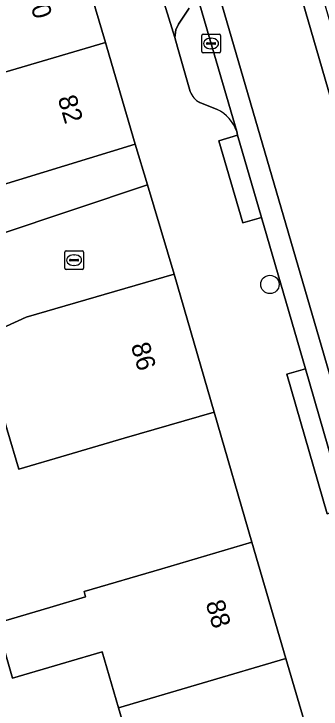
# Model space of a CAD drawing. Extents: x 159262 to 160143, y 383399 to 384319.
# Drawn here: x 159610.56 to 159626.93, y 383964.76 to 384001.77 of the extents above; entities that cross this region are included whole.
import ezdxf

# ---------------------------------------------------------------- set-up
doc = ezdxf.new("R2010")
doc.units = 0
for name, color, linetype in [('IMGEO_Boom', 7, 'Continuous'), ('IMGEO_Erf', 7, 'Continuous'), ('IMGEO_Kolk', 7, 'Continuous'), ('IMGEO_Pand', 7, 'Continuous'), ('IMGEO_Pand_nummerreeks', 7, 'Continuous'), ('IMGEO_Parkeervlak_open', 7, 'Continuous'), ('IMGEO_Rijbaan_lokaal_gesloten', 7, 'Continuous'), ('IMGEO_Verkeerseiland_open', 7, 'Continuous'), ('IMGEO_Voetpad_open', 7, 'Continuous')]:
    doc.layers.add(name, color=color, linetype=linetype)

msp = doc.modelspace()

# ---------------------------------------------------------------- linework, layer by layer
at = {"layer": 'IMGEO_Boom'}
msp.add_circle((159624.2, 383987.368), 0.489, dxfattribs=at)
at = {"layer": 'IMGEO_Erf'}
msp.add_lwpolyline([(159609.702, 383990.016), (159617.673, 383992.679), (159617.029, 383994.834), (159603.519, 383990.7), (159602.655, 383993.46), (159600.265, 383992.746), (159598.549, 383992.233), (159597.74, 383995.059), (159588.938, 383992.59), (159592.618, 383983.277), (159598.01, 383985.458), (159607.28, 383989.207)], close=True, dxfattribs=at)
msp.add_lwpolyline([(159617.064, 383961.667), (159616.136, 383964.825), (159615.258, 383967.811), (159613.337, 383967.246), (159610.494, 383966.411), (159609.635, 383969.336), (159612.478, 383970.171), (159614.385, 383970.731), (159614.301, 383971.02), (159618.438, 383972.236), (159623.235, 383973.646), (159621.234, 383980.578), (159616.434, 383979.18), (159613.365, 383978.285), (159610.819, 383977.543), (159610.212, 383979.628), (159609.303, 383982.748), (159603.513, 383980.094), (159607.678, 383971.028), (159584.038, 383960.27)], dxfattribs=at)
at = {"layer": 'IMGEO_Kolk'}
for p, q in [((159620.567, 383999.769), (159620.567, 384000.621)), ((159620.642, 384000.695), (159621.494, 384000.695)), ((159621.055, 384000.475), (159621.08, 384000.475)), ((159621.568, 384000.621), (159621.568, 383999.769)), ((159620.826, 384000.189), (159620.826, 384000.201)), ((159621.264, 384000.152), (159620.866, 384000.152)), ((159620.869, 384000.238), (159621.267, 384000.238)), ((159621.31, 384000.201), (159621.31, 384000.189)), ((159621.494, 383999.695), (159620.642, 383999.695)), ((159621.078, 383999.915), (159621.053, 383999.915)), ((159613.271, 383988.236), (159613.271, 383989.088)), ((159613.346, 383989.162), (159614.198, 383989.162)), ((159613.759, 383988.942), (159613.784, 383988.942)), ((159614.272, 383989.088), (159614.272, 383988.236)), ((159613.53, 383988.656), (159613.53, 383988.668)), ((159613.968, 383988.619), (159613.57, 383988.619)), ((159613.573, 383988.705), (159613.971, 383988.705)), ((159614.014, 383988.668), (159614.014, 383988.656)), ((159614.198, 383988.162), (159613.346, 383988.162)), ((159613.782, 383988.382), (159613.757, 383988.382))]:
    msp.add_line(p, q, dxfattribs=at)
for points in [[(159620.567, 383999.769), (159620.567, 384000.621)], [(159620.642, 384000.695), (159621.494, 384000.695)], [(159621.568, 384000.621), (159621.568, 383999.769)], [(159621.494, 383999.695), (159620.642, 383999.695)], [(159613.271, 383988.236), (159613.271, 383989.088)], [(159613.346, 383989.162), (159614.198, 383989.162)], [(159614.272, 383989.088), (159614.272, 383988.236)], [(159614.198, 383988.162), (159613.346, 383988.162)]]:
    msp.add_lwpolyline(points, dxfattribs=at)
for centre, radius, start, end in [((159620.644, 384000.619), 0.0765, 91.552, 178.448), ((159620.644, 384000.619), 0.0765, 91.552, 178.448), ((159621.492, 384000.619), 0.0765, 1.552, 88.448), ((159621.492, 384000.619), 0.0765, 1.552, 88.448), ((159620.866, 384000.198), 0.0403, 85.8775, 175.7526), ((159620.863, 384000.188), 0.0366, 178.938, 274.7102), ((159621.267, 384000.195), 0.043, 264.8664, 352.4533), ((159621.271, 384000.2), 0.0386, 1.7309, 96.639), ((159620.644, 383999.771), 0.0765, 181.552, 268.448), ((159620.644, 383999.771), 0.0765, 181.552, 268.448), ((159621.492, 383999.771), 0.0765, 271.552, 358.448), ((159621.492, 383999.771), 0.0765, 271.552, 358.448), ((159613.348, 383989.086), 0.0765, 91.552, 178.448), ((159613.348, 383989.086), 0.0765, 91.552, 178.448), ((159614.196, 383989.086), 0.0765, 1.552, 88.448), ((159614.196, 383989.086), 0.0765, 1.552, 88.448), ((159613.57, 383988.665), 0.0403, 85.8775, 175.7526), ((159613.567, 383988.655), 0.0366, 178.938, 274.7102), ((159613.971, 383988.662), 0.043, 264.8664, 352.4533), ((159613.975, 383988.667), 0.0386, 1.7309, 96.639), ((159613.348, 383988.238), 0.0765, 181.552, 268.448), ((159613.348, 383988.238), 0.0765, 181.552, 268.448), ((159614.196, 383988.238), 0.0765, 271.552, 358.448), ((159614.196, 383988.238), 0.0765, 271.552, 358.448)]:
    msp.add_arc(centre, radius, start, end, dxfattribs=at)
for centre, major_axis, ratio, start_param, end_param in [((159621.054, 384000.195), (-0.387, 0.002), 0.722429, 4.712389, 7.853982), ((159621.079, 384000.195), (-0.39, 0.002), 0.717154, 1.570796, 4.712389), ((159613.758, 383988.662), (-0.387, 0.002), 0.722429, 4.712389, 7.853982), ((159613.783, 383988.662), (-0.39, 0.002), 0.717154, 1.570796, 4.712389)]:
    msp.add_ellipse(centre, major_axis=major_axis, ratio=ratio, start_param=start_param, end_param=end_param, dxfattribs=at)
at = {"layer": 'IMGEO_Pand'}
for points in [[(159599.464, 383995.543), (159615.437, 384000.245), (159613.85, 384005.639), (159605.787, 384003.266), (159605.254, 384003.112), (159602.301, 384002.244), (159603.093, 383999.552), (159593.12, 383996.624), (159592.544, 383998.43), (159580.759, 383994.973), (159582.644, 383990.822), (159588.938, 383992.59), (159597.74, 383995.059)], [(159615.509, 384000), (159615.437, 384000.245), (159599.464, 383995.543), (159597.74, 383995.059), (159598.549, 383992.233), (159600.265, 383992.746), (159602.655, 383993.46), (159603.519, 383990.7), (159617.029, 383994.834)], [(159623.235, 383973.646), (159618.438, 383972.236), (159614.301, 383971.02), (159614.385, 383970.731), (159612.478, 383970.171), (159609.635, 383969.336), (159610.494, 383966.411), (159613.337, 383967.246), (159615.258, 383967.811), (159616.136, 383964.825), (159625.057, 383967.448)], [(159616.136, 383964.825), (159617.064, 383961.667), (159615.141, 383961.102), (159610.851, 383959.841), (159611.745, 383956.801), (159616.035, 383958.062), (159617.938, 383958.622), (159622.082, 383959.84), (159626.879, 383961.25), (159625.057, 383967.448)]]:
    msp.add_lwpolyline(points, close=True, dxfattribs=at)
msp.add_lwpolyline([(159568.187, 383962.73), (159569.09, 383963.023), (159569.26, 383962.497), (159581.93, 383966.6), (159584.038, 383960.27), (159607.678, 383971.028), (159603.513, 383980.094), (159609.303, 383982.748), (159610.212, 383979.628), (159610.819, 383977.543), (159613.365, 383978.285), (159616.434, 383979.18), (159621.234, 383980.578), (159619.095, 383987.923), (159611.223, 383985.63), (159600.104, 383980.555), (159580.294, 383971.513), (159581.043, 383969.342), (159567.313, 383964.895)], dxfattribs=at)
at = {"layer": 'IMGEO_Parkeervlak_open'}
for points in [[(159622.431, 383995.515), (159621.125, 384000), (159620.146, 384003.366)], [(159619.907, 384002.084), (159619.329, 384001.234), (159619.194, 384000.921), (159619.129, 384000.507), (159619.276, 384000), (159619.955, 383997.649)], [(159620.465, 383997.061), (159621.395, 383996.679)]]:
    msp.add_lwpolyline(points, dxfattribs=at)
for centre, radius, start, end in [((159620.908, 383997.96), 1.002, 198.0885, 243.7847), ((159620.576, 383994.907), 1.953, 18.1521, 65.1882)]:
    msp.add_arc(centre, radius, start, end, dxfattribs=at)
at = {"layer": 'IMGEO_Rijbaan_lokaal_gesloten'}
for points in [[(159613.293, 384030.894), (159638.993, 383942.811), (159642.94, 383943.962), (159619.532, 384024.506), (159617.87, 384030.824), (159617.785, 384031.248)], [(159618.934, 384031.339), (159617.785, 384031.248), (159617.87, 384030.824), (159619.532, 384024.506), (159642.94, 383943.962), (159644.044, 383944.284), (159627.798, 384000), (159621.981, 384019.881), (159619.292, 384029.772), (159618.998, 384031.049), (159618.966, 384031.194)], [(159638.993, 383942.811), (159613.293, 384030.894), (159612.139, 384030.718), (159616.014, 384017.294), (159618.072, 384010.257), (159620.044, 384003.715), (159620.146, 384003.366), (159621.125, 384000), (159622.431, 383995.515), (159622.476, 383995.308), (159623.756, 383990.941), (159626.097, 383982.875), (159628.25, 383975.445), (159628.423, 383974.819), (159628.483, 383974.613), (159631.364, 383964.812), (159631.817, 383963.34), (159632.881, 383959.719), (159634.562, 383953.952), (159635.597, 383950.281), (159635.943, 383949.139), (159637.889, 383942.489)]]:
    msp.add_lwpolyline(points, close=True, dxfattribs=at)
at = {"layer": 'IMGEO_Verkeerseiland_open'}
msp.add_lwpolyline([(159619.003, 384004.734), (159618.145, 384005.202), (159617.796, 384005.432), (159617.537, 384005.679), (159619.129, 384000.507), (159619.194, 384000.921), (159619.329, 384001.234), (159619.907, 384002.084)], dxfattribs=at)
at = {"layer": 'IMGEO_Voetpad_open'}
for points in [[(159619.955, 383997.649), (159619.276, 384000), (159619.129, 384000.507), (159617.537, 384005.679), (159616.373, 384009.758), (159611.186, 384027.442)], [(159613.85, 384005.639), (159615.437, 384000.245), (159615.509, 384000), (159617.029, 383994.834), (159617.673, 383992.679), (159619.095, 383987.923), (159621.234, 383980.578), (159623.235, 383973.646), (159625.057, 383967.448), (159626.879, 383961.25), (159627.564, 383958.843), (159629.447, 383952.41), (159629.277, 383952.36), (159630.084, 383949.406), (159630.309, 383949.472), (159631.947, 383943.875), (159634.034, 383936.746), (159635.482, 383931.797), (159637.133, 383926.157), (159638.703, 383920.791), (159638.888, 383920.16), (159633.406, 383906.478)], [(159621.395, 383996.679), (159620.465, 383997.061)], [(159625.098, 383982.586), (159626.097, 383982.875), (159623.756, 383990.941), (159622.758, 383990.648), (159621.478, 383995.015), (159622.476, 383995.308), (159622.431, 383995.515)], [(159628.483, 383974.613), (159628.423, 383974.819), (159628.25, 383975.445), (159627.251, 383975.156), (159625.098, 383982.586)]]:
    msp.add_lwpolyline(points, dxfattribs=at)
for points in [[(159622.476, 383995.308), (159621.478, 383995.015), (159622.758, 383990.648), (159623.756, 383990.941)], [(159619.095, 383987.923), (159617.673, 383992.679), (159609.702, 383990.016), (159607.28, 383989.207), (159598.01, 383985.458), (159600.104, 383980.555), (159611.223, 383985.63)], [(159626.097, 383982.875), (159625.098, 383982.586), (159627.251, 383975.156), (159628.25, 383975.445)]]:
    msp.add_lwpolyline(points, close=True, dxfattribs=at)
for centre, radius, start, end in [((159620.908, 383997.96), 1.002, 198.0885, 243.7847), ((159620.576, 383994.907), 1.953, 18.1521, 65.1882)]:
    msp.add_arc(centre, radius, start, end, dxfattribs=at)

# ---------------------------------------------------------------- texts
at = {"layer": 'IMGEO_Pand_nummerreeks'}
for s, rotation, p in [('80', 286.3921, (159611.249, 384002.859)), ('82', 286.3978, (159612.889, 383997.286)), ('86', 286.2365, (159616.785, 383984.127)), ('88', 286.3807, (159620.767, 383970.411))]:
    msp.add_text(s, height=1, rotation=rotation, dxfattribs=at).set_placement(p)

doc.saveas('drawing.dxf')
